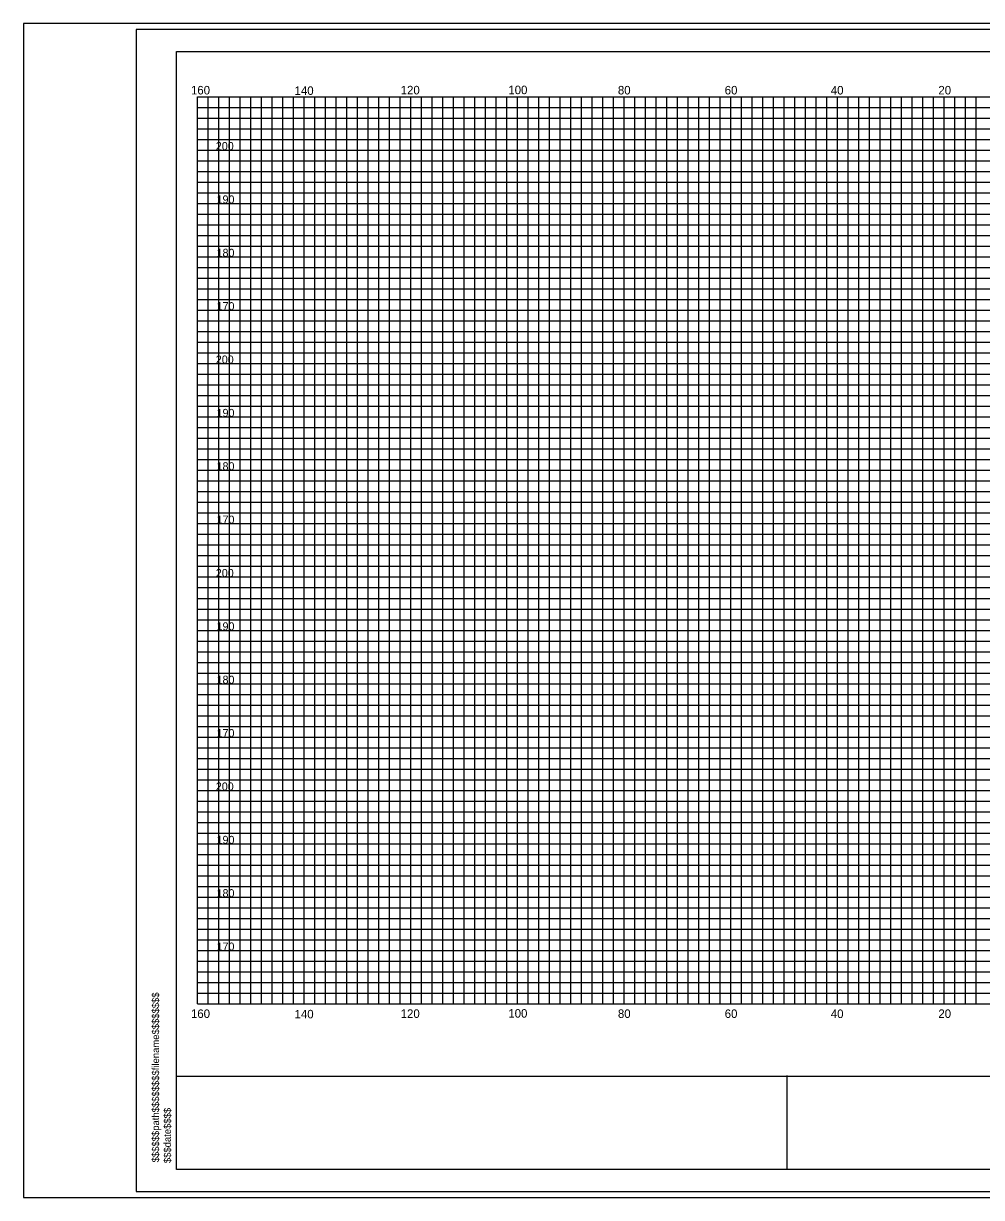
# Model space of a CAD drawing. Extents: x 967 to 1326, y 964 to 3144.
# Drawn here: x 967.4 to 1147, y 2083.7 to 2303.7 of the extents above; entities that cross this region are included whole.
import ezdxf

# ---------------------------------------------------------------- set-up
doc = ezdxf.new("R2010")
doc.units = 0
for name, color, linetype in [('Default', 7, 'Continuous'), ('RD_SHT_Bndy', 7, 'Continuous'), ('RD_SHT_IplotShp', 7, 'Continuous'), ('RD_SHT_MjGrid', 7, 'Continuous'), ('RD_SHT_MnGrid', 7, 'Continuous'), ('RD_SHT_TX', 7, 'Continuous'), ('RD_Sketch1', 7, 'Continuous')]:
    doc.layers.add(name, color=color, linetype=linetype)

msp = doc.modelspace()

# ---------------------------------------------------------------- linework, layer by layer
at = {"layer": 'RD_SHT_Bndy'}
for p, q in [((996.11, 2088.98), (996.11, 2298.46)), ((996.11, 2298.46), (1323.89, 2298.46)), ((996.11, 2106.49), (1323.89, 2106.49)), ((1110.59, 2088.98), (1110.59, 2106.56)), ((1323.89, 2088.98), (996.11, 2088.98))]:
    msp.add_line(p, q, dxfattribs=at)
at = {"layer": 'RD_SHT_IplotShp'}
for points in [[(967.41, 2083.72), (1326.28, 2083.72), (1326.28, 2303.72), (967.41, 2303.72)], [(988.52, 2084.84), (1326.28, 2084.84), (1326.28, 2302.6), (988.52, 2302.6)]]:
    msp.add_lwpolyline(points, close=True, dxfattribs=at)
at = {"layer": 'RD_SHT_MjGrid'}
for p, q in [((1000, 2290), (1320, 2290)), ((1000, 2120), (1000, 2290)), ((1010, 2120), (1010, 2290)), ((1020, 2120), (1020, 2290)), ((1030, 2120), (1030, 2290)), ((1040, 2120), (1040, 2290)), ((1050, 2120), (1050, 2290)), ((1060, 2120), (1060, 2290)), ((1070, 2120), (1070, 2290)), ((1080, 2120), (1080, 2290)), ((1090, 2120), (1090, 2290)), ((1100, 2120), (1100, 2290)), ((1110, 2120), (1110, 2290)), ((1120, 2120), (1120, 2290)), ((1130, 2120), (1130, 2290)), ((1140, 2120), (1140, 2290)), ((1000, 2280), (1320, 2280)), ((1000, 2270), (1320, 2270)), ((1000, 2260), (1320, 2260)), ((1000, 2250), (1320, 2250)), ((1000, 2240), (1320, 2240)), ((1000, 2230), (1320, 2230)), ((1000, 2220), (1320, 2220)), ((1000, 2210), (1320, 2210)), ((1000, 2200), (1320, 2200)), ((1000, 2190), (1320, 2190)), ((1000, 2180), (1320, 2180)), ((1000, 2170), (1320, 2170)), ((1000, 2160), (1320, 2160)), ((1000, 2150), (1320, 2150)), ((1000, 2140), (1320, 2140)), ((1000, 2130), (1320, 2130)), ((1000, 2120), (1320, 2120))]:
    msp.add_line(p, q, dxfattribs=at)
at = {"layer": 'RD_SHT_MnGrid'}
for p, q in [((1000, 2288), (1320, 2288)), ((1002, 2120), (1002, 2290)), ((1004, 2120), (1004, 2290)), ((1006, 2120), (1006, 2290)), ((1008, 2120), (1008, 2290)), ((1012, 2120), (1012, 2290)), ((1014, 2120), (1014, 2290)), ((1016, 2120), (1016, 2290)), ((1018, 2120), (1018, 2290)), ((1022, 2120), (1022, 2290)), ((1024, 2120), (1024, 2290)), ((1026, 2120), (1026, 2290)), ((1028, 2120), (1028, 2290)), ((1032, 2120), (1032, 2290)), ((1034, 2120), (1034, 2290)), ((1036, 2120), (1036, 2290)), ((1038, 2120), (1038, 2290)), ((1042, 2120), (1042, 2290)), ((1044, 2120), (1044, 2290)), ((1046, 2120), (1046, 2290)), ((1048, 2120), (1048, 2290)), ((1052, 2120), (1052, 2290)), ((1054, 2120), (1054, 2290)), ((1056, 2120), (1056, 2290)), ((1058, 2120), (1058, 2290)), ((1062, 2120), (1062, 2290)), ((1064, 2120), (1064, 2290)), ((1066, 2120), (1066, 2290)), ((1068, 2120), (1068, 2290)), ((1072, 2120), (1072, 2290)), ((1074, 2120), (1074, 2290)), ((1076, 2120), (1076, 2290)), ((1078, 2120), (1078, 2290)), ((1082, 2120), (1082, 2290)), ((1084, 2120), (1084, 2290)), ((1086, 2120), (1086, 2290)), ((1088, 2120), (1088, 2290)), ((1092, 2120), (1092, 2290)), ((1094, 2120), (1094, 2290)), ((1096, 2120), (1096, 2290)), ((1098, 2120), (1098, 2290)), ((1102, 2120), (1102, 2290)), ((1104, 2120), (1104, 2290)), ((1106, 2120), (1106, 2290)), ((1108, 2120), (1108, 2290)), ((1112, 2120), (1112, 2290)), ((1114, 2120), (1114, 2290)), ((1116, 2120), (1116, 2290)), ((1118, 2120), (1118, 2290)), ((1122, 2120), (1122, 2290)), ((1124, 2120), (1124, 2290)), ((1126, 2120), (1126, 2290)), ((1128, 2120), (1128, 2290)), ((1132, 2120), (1132, 2290)), ((1134, 2120), (1134, 2290)), ((1136, 2120), (1136, 2290)), ((1138, 2120), (1138, 2290)), ((1142, 2120), (1142, 2290)), ((1144, 2120), (1144, 2290)), ((1146, 2120), (1146, 2290)), ((1000, 2286), (1320, 2286)), ((1000, 2284), (1320, 2284)), ((1000, 2282), (1320, 2282)), ((1000, 2278), (1320, 2278)), ((1000, 2276), (1320, 2276)), ((1000, 2274), (1320, 2274)), ((1000, 2272), (1320, 2272)), ((1000, 2268), (1320, 2268)), ((1000, 2266), (1320, 2266)), ((1000, 2264), (1320, 2264)), ((1000, 2262), (1320, 2262)), ((1000, 2258), (1320, 2258)), ((1000, 2256), (1320, 2256)), ((1000, 2254), (1320, 2254)), ((1000, 2252), (1320, 2252)), ((1000, 2248), (1320, 2248)), ((1000, 2246), (1320, 2246)), ((1000, 2244), (1320, 2244)), ((1000, 2242), (1320, 2242)), ((1000, 2238), (1320, 2238)), ((1000, 2236), (1320, 2236)), ((1000, 2234), (1320, 2234)), ((1000, 2232), (1320, 2232)), ((1000, 2228), (1320, 2228)), ((1000, 2226), (1320, 2226)), ((1000, 2224), (1320, 2224)), ((1000, 2222), (1320, 2222)), ((1000, 2218), (1320, 2218)), ((1000, 2216), (1320, 2216)), ((1000, 2214), (1320, 2214)), ((1000, 2212), (1320, 2212)), ((1000, 2208), (1320, 2208)), ((1000, 2206), (1320, 2206)), ((1000, 2204), (1320, 2204)), ((1000, 2202), (1320, 2202)), ((1000, 2198), (1320, 2198)), ((1000, 2196), (1320, 2196)), ((1000, 2194), (1320, 2194)), ((1000, 2192), (1320, 2192)), ((1000, 2188), (1320, 2188)), ((1000, 2186), (1320, 2186)), ((1000, 2184), (1320, 2184)), ((1000, 2182), (1320, 2182)), ((1000, 2178), (1320, 2178)), ((1000, 2176), (1320, 2176)), ((1000, 2174), (1320, 2174)), ((1000, 2172), (1320, 2172)), ((1000, 2168), (1320, 2168)), ((1000, 2166), (1320, 2166)), ((1000, 2164), (1320, 2164)), ((1000, 2162), (1320, 2162)), ((1000, 2158), (1320, 2158)), ((1000, 2156), (1320, 2156)), ((1000, 2154), (1320, 2154)), ((1000, 2152), (1320, 2152)), ((1000, 2148), (1320, 2148)), ((1000, 2146), (1320, 2146)), ((1000, 2144), (1320, 2144)), ((1000, 2142), (1320, 2142)), ((1000, 2138), (1320, 2138)), ((1000, 2136), (1320, 2136)), ((1000, 2134), (1320, 2134)), ((1000, 2132), (1320, 2132)), ((1000, 2128), (1320, 2128)), ((1000, 2126), (1320, 2126)), ((1000, 2124), (1320, 2124)), ((1000, 2122), (1320, 2122))]:
    msp.add_line(p, q, dxfattribs=at)
at = {"layer": 'RD_Sketch1'}
msp.add_lwpolyline([(967.41, 2083.72), (1326.28, 2083.72), (1326.28, 2303.72), (967.41, 2303.72)], close=True, dxfattribs=at)

# ---------------------------------------------------------------- texts
at = {"layer": 'Default'}
for s, p in [('200', (1003.47, 2280)), ('190', (1003.61, 2270)), ('180', (1003.61, 2260)), ('170', (1003.61, 2250)), ('200', (1003.47, 2240)), ('190', (1003.61, 2230)), ('180', (1003.61, 2220)), ('170', (1003.61, 2210)), ('200', (1003.47, 2200)), ('190', (1003.61, 2190)), ('180', (1003.61, 2180)), ('170', (1003.61, 2170)), ('200', (1003.47, 2160)), ('190', (1003.61, 2150)), ('180', (1003.61, 2140)), ('170', (1003.61, 2130))]:
    msp.add_text(s, height=1.5, dxfattribs=at).set_placement(p)
for s, p in [('$$$$$$path$$$$$$$$filename$$$$$$$$', (992.83, 2090.31)), ('$$$date$$$$', (995.04, 2090.17))]:
    msp.add_text(s, height=1.3258, rotation=90, dxfattribs=at).set_placement(p)
at = {"layer": 'RD_SHT_TX'}
for s, p in [('160', (998.81, 2290.42)), ('140', (1018.23, 2290.34)), ('120', (1038.12, 2290.43)), ('100', (1058.3, 2290.47)), ('80', (1078.84, 2290.42)), ('60', (1098.86, 2290.42)), ('40', (1118.75, 2290.41)), ('20', (1138.91, 2290.42)), ('160', (998.81, 2117.37)), ('140', (1018.23, 2117.29)), ('120', (1038.12, 2117.38)), ('100', (1058.3, 2117.42)), ('80', (1078.84, 2117.37)), ('60', (1098.86, 2117.37)), ('40', (1118.75, 2117.36)), ('20', (1138.91, 2117.37))]:
    msp.add_text(s, height=1.6, dxfattribs=at).set_placement(p)

doc.saveas('drawing.dxf')
